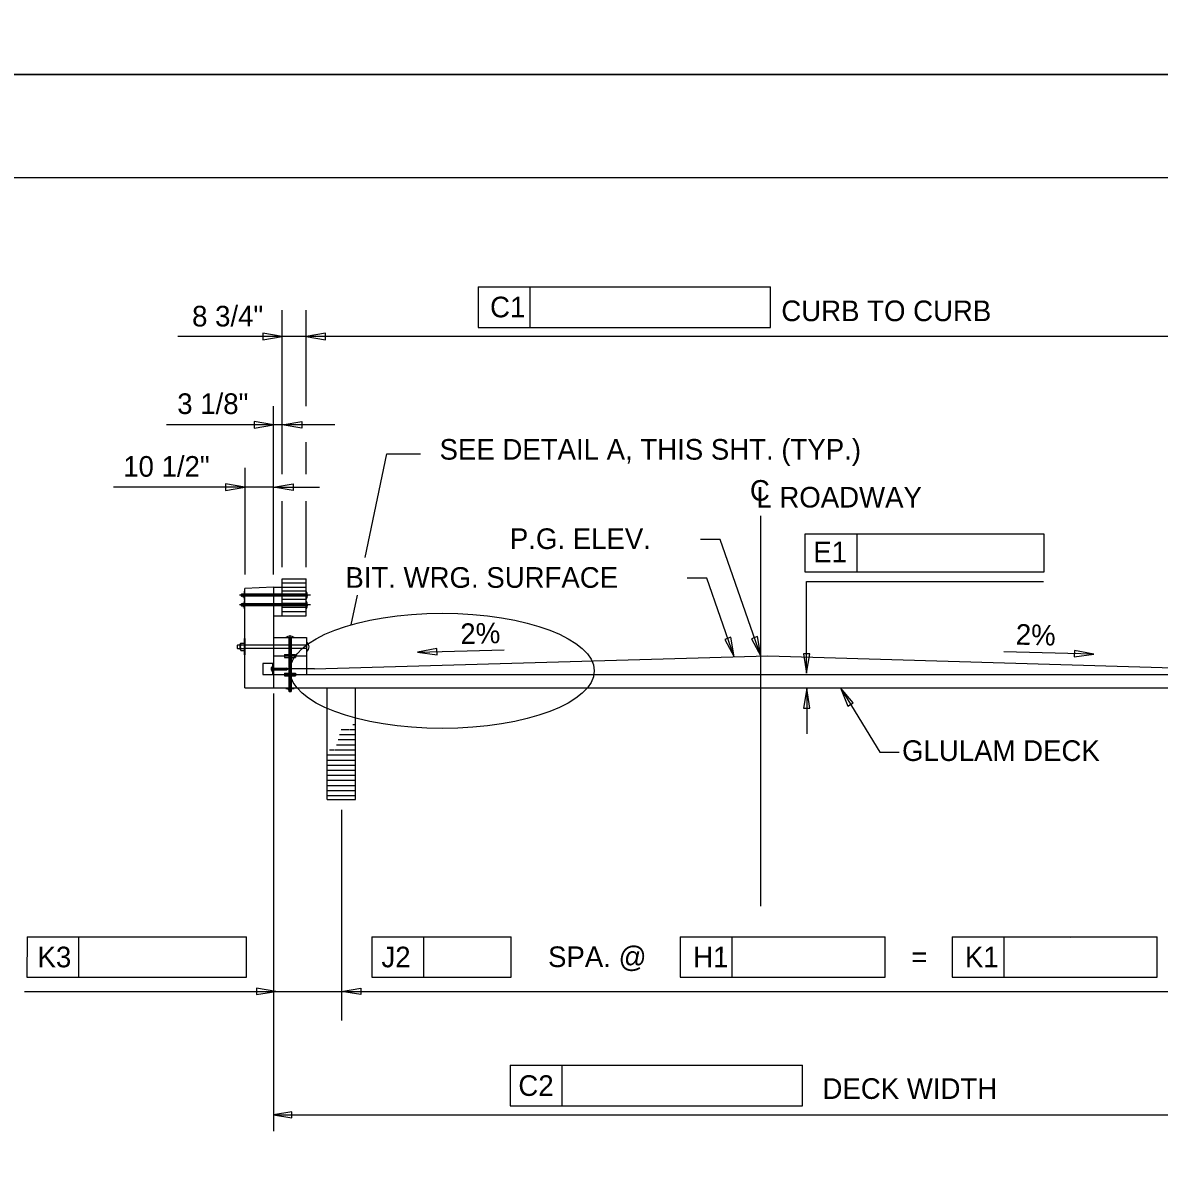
# Model space of a CAD drawing. Extents: x 638263 to 640391, y 293683 to 298655.
# Drawn here: x 638507.9 to 638673.1, y 296494.3 to 296661 of the extents above; entities that cross this region are included whole.
import ezdxf

# ---------------------------------------------------------------- set-up
doc = ezdxf.new("R2010")
doc.units = 0
for name, color, linetype in [('1', 7, 'Continuous'), ('2', 7, 'Continuous'), ('3', 7, 'Continuous'), ('4', 7, 'Continuous'), ('5', 7, 'Continuous'), ('6', 7, 'Continuous'), ('PLT-BNDY', 7, 'Continuous')]:
    doc.layers.add(name, color=color, linetype=linetype)

# ---------------------------------------------------------------- blocks, each defined once
blk = doc.blocks.new('V')
at = {"layer": '1'}
blk.add_line((0, 0), (0, 0), dxfattribs=at)

msp = doc.modelspace()

# ---------------------------------------------------------------- linework, layer by layer
at = {"layer": '2'}
for p, q in [((638475.46, 296638.46), (639261.46, 296638.46)), ((638545.59, 296595.35), (638545.59, 296619.21)), ((638549.06, 296605.23), (638549.06, 296619.21)), ((638574.09, 296616.69), (638616.61, 296616.69)), ((638551.5, 296615.36), (638530.44, 296615.36)), ((638680.18, 296615.36), (638550.26, 296615.36)), ((638544.35, 296580.74), (638544.35, 296605.23)), ((638553.26, 296602.52), (638528.77, 296602.52)), ((638549.06, 296595.35), (638549.06, 296600)), ((638557.67, 296583.22), (638560.81, 296598.32)), ((638560.81, 296598.32), (638565.72, 296598.32)), ((638540.18, 296596.26), (638540.18, 296580.74)), ((638544.35, 296593.46), (638521.04, 296593.46)), ((638544.35, 296593.46), (638551.01, 296593.46)), ((638545.59, 296581.83), (638545.59, 296591.44)), ((638549.06, 296581.83), (638549.06, 296591.44)), ((638615.22, 296532.53), (638615.22, 296589.29)), ((638609.27, 296585.85), (638606.44, 296585.85)), ((638615.22, 296568.9), (638609.27, 296585.85)), ((638621.65, 296581.11), (638621.65, 296586.65)), ((638621.65, 296586.65), (638629.22, 296586.65)), ((638629.22, 296586.65), (638656.36, 296586.65)), ((638629.22, 296581.11), (638629.22, 296586.65)), ((638656.36, 296586.65), (638656.36, 296581.11)), ((638656.36, 296581.11), (638621.65, 296581.11)), ((638544.35, 296578.93), (638540.18, 296578.73)), ((638544.35, 296578.93), (638545.59, 296578.93)), ((638544.35, 296578.93), (638544.35, 296571.59)), ((638545.59, 296574.76), (638545.59, 296580.11)), ((638545.59, 296580.11), (638549.06, 296580.11)), ((638545.59, 296579.52), (638549.06, 296579.52)), ((638545.59, 296578.93), (638549.06, 296578.93)), ((638549.06, 296574.76), (638549.06, 296580.11)), ((638607.34, 296580.21), (638604.51, 296580.21)), ((638611.35, 296568.79), (638607.34, 296580.21)), ((638621.86, 296566.39), (638621.86, 296579.74)), ((638621.86, 296579.74), (638656.32, 296579.74)), ((638539.65, 296577.86), (638539.68, 296577.88)), ((638539.65, 296577.86), (638539.65, 296577.61)), ((638539.65, 296577.61), (638539.68, 296577.58)), ((638539.85, 296577.88), (638539.68, 296577.88)), ((638539.85, 296577.58), (638539.68, 296577.58)), ((638539.85, 296577.9), (638539.85, 296577.56)), ((638539.89, 296577.96), (638540.09, 296577.96)), ((638539.89, 296577.85), (638540.09, 296577.85)), ((638539.89, 296577.62), (638540.09, 296577.62)), ((638539.89, 296577.5), (638540.09, 296577.5)), ((638540.09, 296577.14), (638540.09, 296578.33)), ((638540.09, 296578.33), (638540.18, 296578.33)), ((638540.09, 296577.5), (638540.09, 296577.96)), ((638540.18, 296564.26), (638540.18, 296578.73)), ((638549.06, 296577.88), (638540.18, 296577.88)), ((638549.06, 296577.59), (638540.18, 296577.59)), ((638549.06, 296578.33), (638545.59, 296578.33)), ((638555.64, 296573.45), (638556.53, 296577.74)), ((638539.65, 296576.47), (638539.68, 296576.49)), ((638539.65, 296576.47), (638539.65, 296576.22)), ((638539.65, 296576.22), (638539.68, 296576.2)), ((638539.85, 296576.49), (638539.68, 296576.49)), ((638539.85, 296576.2), (638539.68, 296576.2)), ((638539.85, 296576.51), (638539.85, 296576.17)), ((638539.89, 296576.57), (638540.09, 296576.57)), ((638539.89, 296576.46), (638540.09, 296576.46)), ((638539.89, 296576.23), (638540.09, 296576.23)), ((638539.89, 296576.11), (638540.09, 296576.11)), ((638540.18, 296577.14), (638540.09, 296577.14)), ((638540.09, 296577.14), (638540.09, 296577.14)), ((638540.09, 296575.75), (638540.09, 296576.94)), ((638540.09, 296576.94), (638540.18, 296576.94)), ((638540.09, 296576.11), (638540.09, 296576.57)), ((638540.18, 296575.75), (638540.09, 296575.75)), ((638540.09, 296575.75), (638540.09, 296575.75)), ((638540.18, 296577.14), (638540.18, 296577.14)), ((638549.06, 296576.49), (638540.18, 296576.49)), ((638549.06, 296576.2), (638540.18, 296576.2)), ((638540.18, 296575.75), (638540.18, 296575.75)), ((638549.06, 296577.14), (638545.59, 296577.14)), ((638549.06, 296576.55), (638545.59, 296576.55)), ((638549.06, 296575.95), (638545.59, 296575.95)), ((638544.35, 296574.76), (638549.06, 296574.76)), ((638545.59, 296575.35), (638549.06, 296575.35)), ((638539.5, 296569.83), (638539.5, 296570.66)), ((638539.59, 296570.52), (638540.08, 296570.52)), ((638539.6, 296570.79), (638540.08, 296570.79)), ((638540.08, 296571.43), (638540.08, 296569.05)), ((638540.18, 296571.43), (638540.08, 296571.43)), ((638540.08, 296570.79), (638540.08, 296569.69)), ((638540.18, 296570.52), (638540.08, 296570.52)), ((638540.18, 296571.43), (638540.18, 296569.05)), ((638544.35, 296571.59), (638544.35, 296568.91)), ((638544.35, 296571.59), (638549.12, 296571.59)), ((638546.58, 296571.59), (638546.58, 296564.26)), ((638546.74, 296563.75), (638546.74, 296571.93)), ((638546.88, 296571.59), (638546.88, 296564.26)), ((638549.12, 296571.59), (638549.12, 296568.91)), ((638539.06, 296570.44), (638539.1, 296570.49)), ((638539.06, 296570.44), (638539.06, 296570.04)), ((638539.06, 296570.04), (638539.1, 296570)), ((638539.5, 296570.49), (638539.1, 296570.49)), ((638539.1, 296570), (638539.5, 296570)), ((638539.5, 296570.49), (638539.5, 296570.49)), ((638539.59, 296569.97), (638540.08, 296569.97)), ((638539.6, 296569.69), (638540.08, 296569.69)), ((638540.18, 296569.97), (638540.08, 296569.97)), ((638540.08, 296569.05), (638540.18, 296569.05)), ((638549.12, 296570.49), (638540.18, 296570.49)), ((638549.12, 296570), (638540.18, 296570)), ((638544.35, 296568.91), (638544.35, 296566.22)), ((638544.35, 296568.91), (638549.12, 296568.91)), ((638545.94, 296569.1), (638545.94, 296568.7)), ((638545.94, 296569.1), (638547.52, 296569.1)), ((638547.52, 296569.1), (638547.52, 296568.7)), ((638549.12, 296568.91), (638549.12, 296566.22)), ((638565.27, 296569.46), (638577.88, 296569.79)), ((638663.59, 296569.16), (638650.54, 296569.53)), ((638542.76, 296567.81), (638542.76, 296566.22)), ((638544.35, 296567.81), (638542.76, 296567.81)), ((638544.11, 296567.21), (638543.97, 296567.21)), ((638543.97, 296567.21), (638543.97, 296566.82)), ((638544.11, 296567.32), (638544.17, 296567.32)), ((638544.11, 296567.32), (638544.11, 296566.72)), ((638544.17, 296567.81), (638544.17, 296566.22)), ((638545.94, 296568.7), (638547.52, 296568.7)), ((638542.76, 296566.22), (638544.35, 296566.22)), ((638544.11, 296566.82), (638543.97, 296566.82)), ((638544.11, 296566.72), (638544.17, 296566.72)), ((638544.17, 296567.14), (638546.28, 296567.14)), ((638544.17, 296566.89), (638546.28, 296566.89)), ((638549.12, 296567.03), (638544.35, 296567.03)), ((638544.35, 296566.22), (638544.35, 296564.26)), ((638545.94, 296566.42), (638545.94, 296566.03)), ((638545.94, 296566.42), (638547.52, 296566.42)), ((638545.94, 296566.03), (638547.52, 296566.03)), ((638546.5, 296567.02), (638546.28, 296567.14)), ((638546.5, 296567.02), (638546.28, 296566.89)), ((638547.52, 296566.42), (638547.52, 296566.03)), ((638550.31, 296567.03), (638549.12, 296567.03)), ((638546.13, 296564.26), (638546.13, 296564.26)), ((638546.13, 296564.26), (638546.13, 296564.16)), ((638546.13, 296564.17), (638546.13, 296564.17)), ((638546.13, 296564.16), (638547.33, 296564.16)), ((638546.51, 296563.97), (638546.51, 296564.16)), ((638546.55, 296564.26), (638546.55, 296564.16)), ((638546.91, 296563.93), (638546.56, 296563.93)), ((638546.58, 296563.93), (638546.58, 296563.75)), ((638546.61, 296563.91), (638546.85, 296563.91)), ((638546.61, 296563.88), (638546.85, 296563.88)), ((638546.61, 296563.85), (638546.85, 296563.85)), ((638546.62, 296563.97), (638546.62, 296564.16)), ((638546.85, 296563.97), (638546.85, 296564.16)), ((638546.88, 296563.93), (638546.88, 296563.75)), ((638546.91, 296564.26), (638546.91, 296564.16)), ((638546.96, 296563.97), (638546.96, 296564.16)), ((638547.33, 296564.16), (638547.33, 296564.26)), ((638621.88, 296564.17), (638621.88, 296557.57)), ((638626.78, 296564.26), (638632.5, 296554.92)), ((638544.35, 296563.44), (638544.35, 296499.8)), ((638546.61, 296563.73), (638546.58, 296563.75)), ((638546.61, 296563.83), (638546.85, 296563.83)), ((638546.61, 296563.81), (638546.85, 296563.81)), ((638546.61, 296563.78), (638546.85, 296563.78)), ((638546.61, 296563.75), (638546.85, 296563.75)), ((638546.85, 296563.73), (638546.61, 296563.73)), ((638546.85, 296563.73), (638546.88, 296563.75)), ((638632.5, 296554.92), (638635.34, 296554.92)), ((638554.2, 296546.55), (638554.2, 296517.29)), ((638508.48, 296528.09), (638508.47, 296522.19)), ((638508.48, 296528.09), (638516.04, 296528.09)), ((638516.04, 296528.09), (638540.41, 296528.09)), ((638516.04, 296522.19), (638516.04, 296528.09)), ((638540.4, 296522.19), (638540.41, 296528.09)), ((638558.63, 296528.09), (638558.63, 296522.19)), ((638558.63, 296528.09), (638566.19, 296528.09)), ((638566.19, 296528.09), (638578.9, 296528.09)), ((638566.19, 296522.19), (638566.19, 296528.09)), ((638578.9, 296522.19), (638578.9, 296528.09)), ((638603.49, 296528.09), (638603.48, 296522.19)), ((638603.49, 296528.09), (638611.05, 296528.09)), ((638611.04, 296522.19), (638611.05, 296528.09)), ((638611.05, 296528.09), (638633.29, 296528.09)), ((638633.29, 296522.19), (638633.29, 296528.09)), ((638643.04, 296528.09), (638650.6, 296528.09)), ((638643.04, 296528.09), (638643.04, 296522.19)), ((638650.6, 296528.09), (638672.85, 296528.09)), ((638650.6, 296522.19), (638650.6, 296528.09)), ((638672.84, 296522.19), (638672.85, 296528.09)), ((638554.2, 296526.05), (638554.2, 296515.89)), ((638508.47, 296522.19), (638540.4, 296522.19)), ((638558.63, 296522.19), (638578.9, 296522.19)), ((638603.48, 296522.19), (638633.29, 296522.19)), ((638643.04, 296522.19), (638672.84, 296522.19)), ((638508.11, 296520.14), (638544.35, 296520.14)), ((638544.35, 296520.14), (638679.31, 296520.14)), ((638578.76, 296509.39), (638578.76, 296503.48)), ((638578.76, 296509.39), (638586.32, 296509.39)), ((638586.32, 296509.39), (638621.28, 296509.39)), ((638586.32, 296503.48), (638586.32, 296509.39)), ((638621.28, 296503.48), (638621.28, 296509.39)), ((638578.76, 296503.48), (638621.28, 296503.48)), ((638544.35, 296502.17), (638686.09, 296502.17))]:
    msp.add_line(p, q, dxfattribs=at)
for points in [[(638542.76, 296615.84), (638542.76, 296614.89), (638545.59, 296615.36)], [(638541.52, 296602.99), (638541.52, 296602.05), (638544.35, 296602.52)], [(638548.43, 296602.99), (638548.43, 296602.05), (638545.59, 296602.52)], [(638537.35, 296593.93), (638537.35, 296592.99), (638540.18, 296593.46)], [(638547.19, 296593.93), (638547.19, 296592.99), (638544.35, 296593.46)], [(638610.86, 296571.62), (638609.97, 296571.31), (638611.35, 296568.79)], [(638614.73, 296571.73), (638613.84, 296571.42), (638615.22, 296568.9)], [(638568.11, 296569.06), (638568.09, 296570.01), (638565.27, 296569.46)], [(638622.33, 296569.22), (638621.39, 296569.22), (638621.86, 296566.39)], [(638660.81, 296569.71), (638660.78, 296568.77), (638663.63, 296569.17)], [(638621.41, 296561.33), (638622.35, 296561.33), (638621.88, 296564.17)], [(638627.86, 296561.59), (638628.66, 296562.09), (638626.78, 296564.26)], [(638541.84, 296520.62), (638541.84, 296519.67), (638544.67, 296520.14)], [(638557.03, 296520.62), (638557.03, 296519.67), (638554.2, 296520.14)], [(638546.98, 296501.73), (638546.98, 296502.61), (638544.35, 296502.17)]]:
    msp.add_lwpolyline(points, close=True, dxfattribs=at)
for centre, radius, start, end in [((638539.92, 296577.9), 0.0634, 114.702, 244.7086), ((638540.05, 296577.73), 0.195, 144.5002, 216.0965), ((638539.92, 296577.56), 0.0631, 114.1235, 245.2701), ((638548.4, 296577.73), 0.898, 318.5212, 41.4788), ((638539.92, 296576.51), 0.0634, 114.702, 244.7086), ((638540.05, 296576.34), 0.195, 144.5002, 216.0965), ((638539.92, 296576.17), 0.0631, 114.1235, 245.2701), ((638548.4, 296576.34), 0.898, 318.5212, 41.4788), ((638539.66, 296570.65), 0.151, 113.4078, 245.8697), ((638539.97, 296570.24), 0.469, 143.8906, 215.5087), ((638546.74, 296570.91), 0.898, 48.5212, 131.4788), ((638548.65, 296570.24), 0.852, 303.2799, 56.719), ((638539.66, 296569.83), 0.152, 115.2831, 249.0228), ((638546.56, 296563.99), 0.0631, 204.7299, 335.8765), ((638546.74, 296564.12), 0.195, 233.9035, 305.4998), ((638546.91, 296563.99), 0.0634, 205.2914, 335.298)]:
    msp.add_arc(centre, radius, start, end, dxfattribs=at)
msp.add_ellipse((638568.87, 296566.74), major_axis=(-22.11, 0), ratio=0.378749, dxfattribs=at)
at = {"layer": '3'}
for p, q in [((638544.35, 296578.93), (638544.35, 296564.26)), ((638549.69, 296577.73), (638539.39, 296577.73)), ((638549.69, 296576.35), (638539.39, 296576.35)), ((638550.26, 296567.04), (638616.21, 296568.93)), ((638616.21, 296568.93), (638680.18, 296567.04)), ((638544.35, 296566.22), (638686.09, 296566.22)), ((638540.18, 296564.26), (638690.26, 296564.26)), ((638552.15, 296548.02), (638552.15, 296564.26)), ((638552.15, 296564.26), (638556.25, 296564.26)), ((638556.25, 296548.02), (638556.25, 296564.26)), ((638555.89, 296558.95), (638556.25, 296558.95)), ((638553.95, 296557.47), (638556.25, 296557.47)), ((638554.17, 296558.21), (638555.4, 296558.21)), ((638555.5, 296558.21), (638556.25, 296558.21)), ((638553.48, 296556), (638556.25, 296556)), ((638553.72, 296556.74), (638556.25, 296556.74)), ((638552.15, 296554.52), (638556.25, 296554.52)), ((638552.46, 296555.26), (638553.17, 296555.26)), ((638553.24, 296555.26), (638556.25, 296555.26)), ((638552.15, 296553.78), (638556.25, 296553.78)), ((638552.15, 296553.05), (638556.25, 296553.05)), ((638552.15, 296552.31), (638556.25, 296552.31)), ((638552.15, 296551.57), (638556.25, 296551.57)), ((638552.15, 296550.83), (638556.25, 296550.83)), ((638552.15, 296550.09), (638556.25, 296550.09)), ((638552.15, 296549.35), (638556.25, 296549.35)), ((638552.15, 296548.62), (638556.25, 296548.62)), ((638552.15, 296548.02), (638556.25, 296548.02))]:
    msp.add_line(p, q, dxfattribs=at)
at = {"layer": '4'}
for p, q in [((638574.1, 296622.6), (638574.09, 296616.69)), ((638574.1, 296622.6), (638581.66, 296622.6)), ((638581.65, 296616.69), (638581.66, 296622.6)), ((638581.66, 296622.6), (638616.61, 296622.6)), ((638616.61, 296616.69), (638616.61, 296622.6))]:
    msp.add_line(p, q, dxfattribs=at)
at = {"layer": '6'}
msp.add_lwpolyline([(638551.9, 296614.89), (638551.9, 296615.84), (638549.06, 296615.36)], close=True, dxfattribs=at)
at = {"layer": 'PLT-BNDY'}
for points in [[(638435.46, 297247.46), (639276.46, 297247.46), (639276.46, 296653.46), (638435.46, 296653.46)], [(638435.46, 296653.46), (639276.46, 296653.46), (639276.46, 296059.46), (638435.46, 296059.46)]]:
    msp.add_lwpolyline(points, close=True, dxfattribs=at)

# ---------------------------------------------------------------- block references
at = {"layer": '2', "xscale": 0.7874015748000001, "yscale": 0.7874015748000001}
for p in [(638642.8, 296586.65), (638528.23, 296528.09)]:
    msp.add_blockref('V', p, dxfattribs=at)
at = {"layer": '5', "xscale": 0.7874015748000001, "yscale": 0.7874015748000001}
for p in [(638599.14, 296622.6), (638572.55, 296528.09), (638622.17, 296528.09), (638660.28, 296527.9), (638603.81, 296509.39)]:
    msp.add_blockref('V', p, dxfattribs=at)

# ---------------------------------------------------------------- texts
at = {"layer": '2'}
for s, p in [('CURB TO CURB', (638618.19, 296617.59)), ('SEE DETAIL A, THIS SHT. (TYP.)', (638568.48, 296597.45)), ('C', (638613.62, 296591.48)), ('L ROADWAY', (638614.56, 296590.49)), ('P.G. ELEV.', (638578.71, 296584.46)), ('E1', (638622.83, 296582.54)), ('BIT. WRG. SURFACE', (638554.78, 296578.82)), ('GLULAM DECK', (638635.75, 296553.64)), ('SPA. @', (638584.26, 296523.67)), ('=', (638637.09, 296523.67)), ('DECK WIDTH', (638624.18, 296504.5))]:
    msp.add_text(s, height=3, dxfattribs=at).set_placement(p)
for s, rotation, p in [('2%', 1.5039, (638571.55, 296570.62)), ('2%', 358.4961, (638652.25, 296570.56)), ('K3', 359.9382, (638510.01, 296523.64)), ('J2', 359.9382, (638560.03, 296523.64)), ('H1', 359.9382, (638605.37, 296523.64)), ('K1', 359.9382, (638644.89, 296523.64)), ('C2', 359.9382, (638579.94, 296504.94))]:
    msp.add_text(s, height=3, rotation=rotation, dxfattribs=at).set_placement(p)
at = {"layer": '4'}
msp.add_text('C1', height=3, rotation=359.9382, dxfattribs=at).set_placement((638575.83, 296618.15))
for s, p in [('8 3/4"', (638532.49, 296616.82)), ('3 1/8"', (638530.33, 296604.09)), ('10 1/2"', (638522.47, 296594.97))]:
    msp.add_text(s, height=3, dxfattribs=at).set_placement(p)

doc.saveas('drawing.dxf')
